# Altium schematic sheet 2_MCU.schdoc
size 309 x 223 mm; Symbol: Artery_A4; Device: Artery_A4; @Project Name: AT-START-M412; @Page Count: 4; @Create Date: 2024-06-20; Company: Artery Technology; Drawed: SD; Version: 1.0; Page Size: A4; @Update Date: 2024-08-06; @Page No: 2; @Schematic Name: AT-START-M412-V1.0; @Page Name: MCU; @Board Name: AT-START-M412-V1.0; @Create Time: 16:55:15; @Update Time: 16:25:14
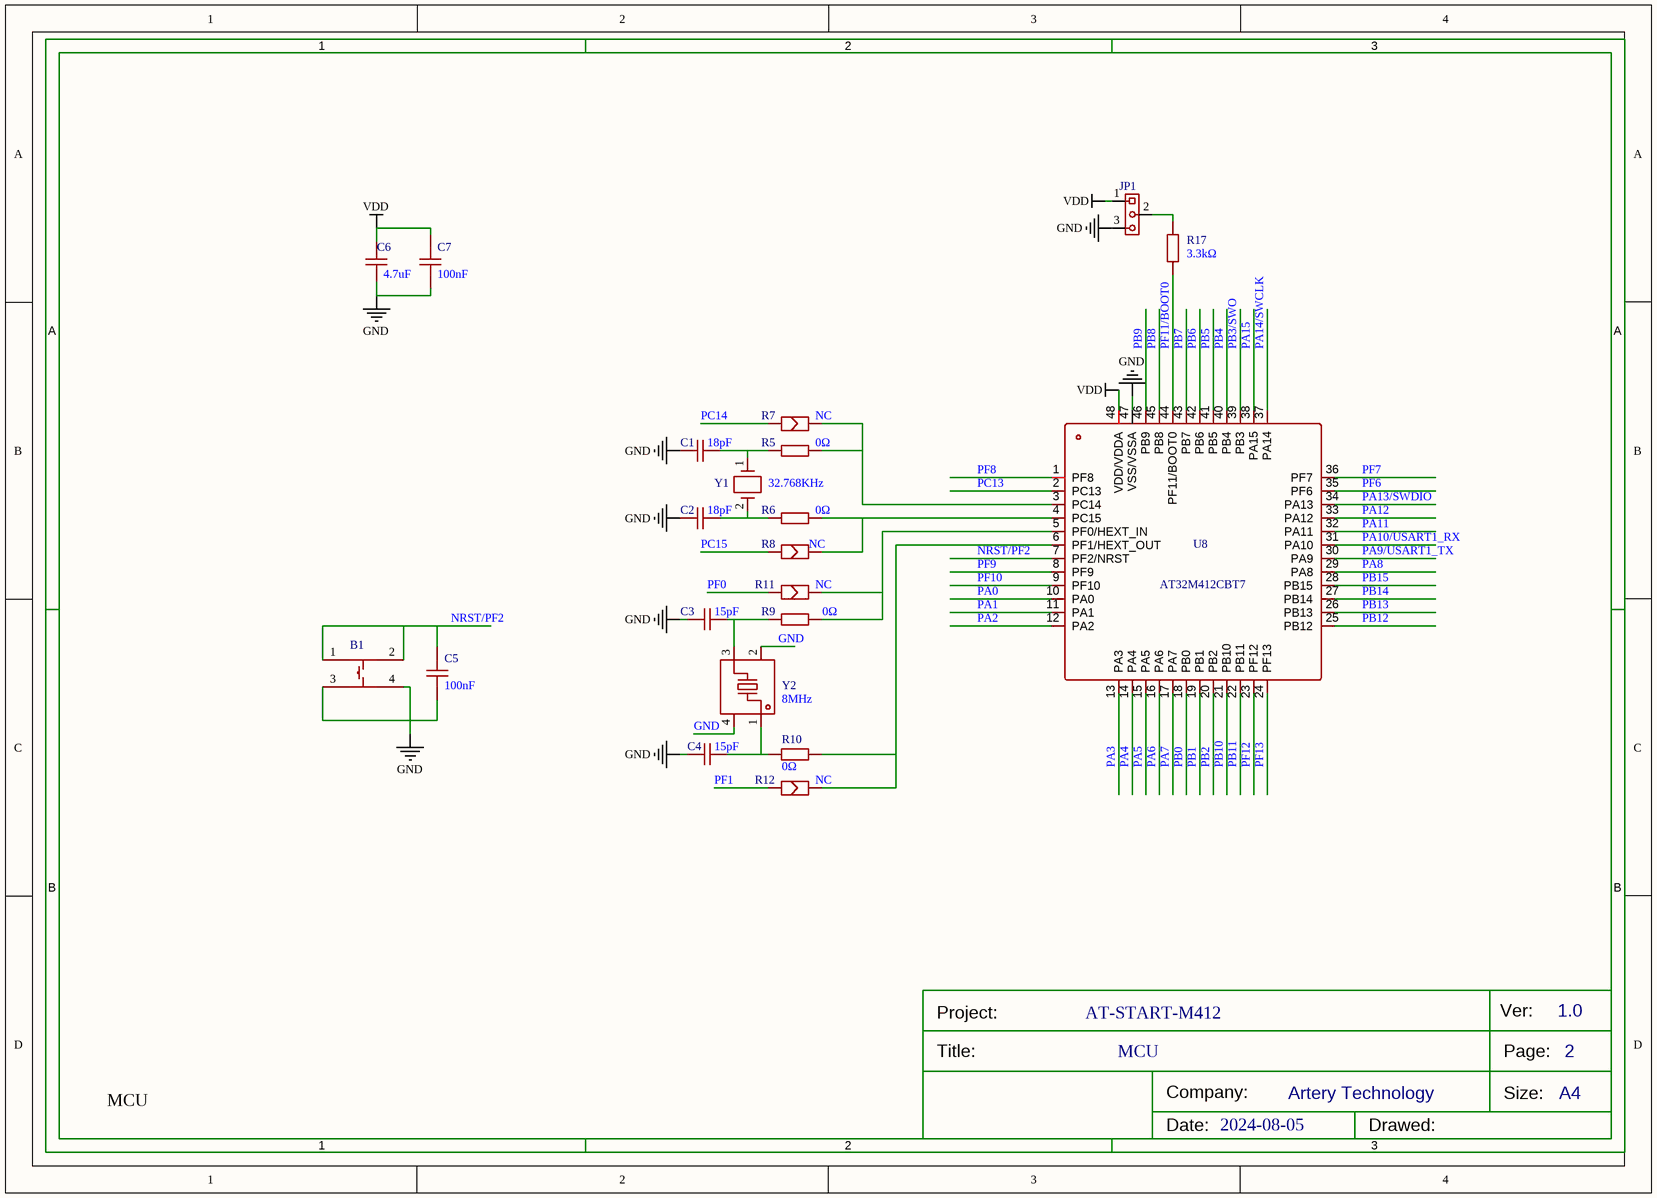
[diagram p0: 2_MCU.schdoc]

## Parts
B1  TS-1002S-05026C  [KEY-SMD_4P-L6.0-W6.0-P4.50-LS9.0]  (value not drawn)
C1  18pF  [C0603]  (value not drawn)
C2  18pF  [C0603]  (value not drawn)
C3  15pF  [C0603]  (value not drawn)
C4  15pF  [C0603]  (value not drawn)
C5  100nF  [C0603]  (value not drawn)
C6  4.7uF  [C0603]  (value not drawn)
C7  100nF  [C0603]  (value not drawn)
JP1  2.54-1*3P针  [HDR-TH_3P-P2.54-V-M-1]  (value not drawn)
R5  0Ω  [SB-PAD_2]  (value not drawn)
R6  0Ω  [SB-PAD_2]  (value not drawn)
R7  NC  [SB-PAD_2]  (value not drawn)
R8  NC  [SB-PAD_2]  (value not drawn)
R9  0Ω  [SB-PAD_2]  (value not drawn)
R10  0Ω  [SB-PAD_2]  (value not drawn)
R11  NC  [SB-PAD_2]  (value not drawn)
R12  NC  [SB-PAD_2]  (value not drawn)
R17  3.3kΩ  [R0603]  (value not drawn)
U8  AT32M412CxT7  [LQFP-48_L7.0-W7.0-P0.50-LS9.0-BL]  (value not drawn)
Y1  32.768KHz  [XTAL_SOP - FC-12M]  (value not drawn)
Y2  8MHz  [CRYSTAL-SMD_4P-L3.2-W2.5-BL]  (value not drawn)

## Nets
GND: B1.3 B1.4 C1.1 C2.1 C3.1 C4.1 C5.1 C6.1 C7.1 JP1.3 U8.47(VSS/VSSA) Y2.2(GND) Y2.4(GND)
VDD: C6.2 C7.2 JP1.1 U8.48(VDD/VDDA)
NRST/PF2: B1.1 B1.2 C5.2 U8.7(PF2/NRST)
PA0: U8.10(PA0)
PA1: U8.11(PA1)
PA2: U8.12(PA2)
PA3: U8.13(PA3)
PA4: U8.14(PA4)
PA5: U8.15(PA5)
PA6: U8.16(PA6)
PA7: U8.17(PA7)
PA8: U8.29(PA8)
PA9/USART1_TX: U8.30(PA9)
PA10/USART1_RX: U8.31(PA10)
PA11: U8.32(PA11)
PA12: U8.33(PA12)
PA13/SWDIO: U8.34(PA13)
PA14/SWCLK: U8.37(PA14)
PA15: U8.38(PA15)
PB0: U8.18(PB0)
PB1: U8.19(PB1)
PB2: U8.20(PB2)
PB3/SWO: U8.39(PB3)
PB4: U8.40(PB4)
PB5: U8.41(PB5)
PB6: U8.42(PB6)
PB7: U8.43(PB7)
PB8: U8.45(PB8)
PB9: U8.46(PB9)
PB10: U8.21(PB10)
PB11: U8.22(PB11)
PB12: U8.25(PB12)
PB13: U8.26(PB13)
PB14: U8.27(PB14)
PB15: U8.28(PB15)
PC13: U8.2(PC13)
PC14: R7.1
PC15: R8.1
PF0: R11.1
PF1: R12.1
PF6: U8.35(PF6)
PF7: U8.36(PF7)
PF8: U8.1(PF8)
PF9: U8.8(PF9)
PF10: U8.9(PF10)
PF11/BOOT0: R17.1 U8.44(PF11/BOOT0)
PF12: U8.23(PF12)
PF13: U8.24(PF13)
NetC1_2: C1.2 R5.1 Y1.1
NetC2_2: C2.2 R6.1 Y1.2
NetC3_2: C3.2 R9.1 Y2.3
NetC4_2: C4.2 R10.1 Y2.1
NetJP1_2: JP1.2 R17.2
NetR5_2: R5.2 R7.2 U8.3(PC14)
NetR6_2: R6.2 R8.2 U8.4(PC15)
NetR9_2: R9.2 R11.2 U8.5(PF0/HEXT_IN)
NetR10_2: R10.2 R12.2 U8.6(PF1/HEXT_OUT)

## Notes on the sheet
- (near U8) AT32M412CBT7
- AT-START-M412
- MCU
- 2024-08-05

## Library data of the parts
B1 = TS-1002S-05026C: 电路结构:单刀单掷;按钮形状:圆形按钮;安装方式:立贴;开关长度:6mm;开关宽度:6mm;开关高度:5mm;触点电流:50mA;额定电压(DC):12V;带灯:-;机械寿命:-;; Manufacturer: XUNPU(讯普); Add into BOM: yes; Circuit: 单刀单掷; Actuator Style: 圆形按钮; Switch Length: 6mm; Switch Height: 5mm; Contact Current: 50mA; Voltage Rating (DC): 12V; Origin Footprint: KEY_SOP_6*6
C1 C2 = CL10C180JB8NNNC: 容值:18pF;精度:±5%;额定电压:50V;材质(温度系数):C0G;; Manufacturer: SAMSUNG(三星); Add into BOM: yes; Tolerance: ±5%; Voltage Rated: 50V; Temperature Coefficient: C0G
C3 C4 = CL10C150JB8NNNC: 容值:15pF;精度:±5%;额定电压:50V;材质(温度系数):C0G;; Manufacturer: SAMSUNG(三星); Add into BOM: yes; Tolerance: ±5%; Voltage Rated: 50V; Temperature Coefficient: C0G
C5 C7 = CC0603KRX7R9BB104: 容值:100nF;精度:±10%;额定电压:50V;材质(温度系数):X7R;; Manufacturer: YAGEO(国巨); Add into BOM: yes; Tolerance: ±10%; Voltage Rated: 50V; Temperature Coefficient: X7R
C6 = CL10A475KO8NNNC: 容值:4.7uF;精度:±10%;额定电压:16V;材质(温度系数):X5R;; Manufacturer: SAMSUNG(三星); Add into BOM: yes; Tolerance: ±10%; Voltage Rated: 16V; Temperature Coefficient: X5R
JP1 = 2.54-1*3P针: 插针结构:1x3P;间距:2.54mm;行距:-;圆针/方针:方针;安装类型:直插;排数:单排;总PIN位数:3P;额定电流:3A;额定电压:-;配合针长度:-;塑高:-;端接针长度:-;触头材质:-;触头镀层:-;工作温度范围:-40℃~+105℃;颜色:黑色;; Manufacturer: BOOMELE(博穆精密); Symbol: Header-Male-2.54_1x3; Add into BOM: yes; Pin Structure: 1x3P; Pitch: 2.54mm; Circluar Pins/Square Pins: 方针; Current Rating (Max): 3A; Origin Footprint: HEADER 1X2
R5 R6 R9 R10 = 0603WAF0000T5E: 电阻类型:厚膜电阻;阻值:0Ω;精度:±1%;功率:100mW;最大工作电压:75V;; Manufacturer: UNI-ROYAL(厚声); Add into BOM: yes; Tolerance: ±1%; Power(Watts): 100mW; Overload Voltage (Max): 75V; Origin Footprint: SB-PAD
R7 R8 R11 R12 = SB_PAD: 贴片电阻0R,1/10W,5%,0603; Symbol: SB-PAD; Convert to PCB: yes
R17 = 0603WAF3301T5E: 电阻类型:厚膜电阻;阻值:3.3kΩ;精度:±1%;功率:100mW;最大工作电压:75V;温度系数:±100ppm/℃;; Manufacturer: UNI-ROYAL(厚声); Symbol: 0603WAF1002T5E; Add into BOM: yes; Tolerance: ±1%; Power(Watts): 100mW; Overload Voltage (Max): 75V
U8 = AT32M412CxT7: 由官方提供; Manufacturer: ArteryTechnology; Add into BOM: yes
Y1 = 32.768KHz: 32.768KHz贴片晶振 TZ2528C 2012 12.5pf 20ppm; Symbol: 32.768KHz,CRY,30PPM,Size_3X8; Add into BOM: yes
Y2 = CJ13-080001210B20: 频率:8MHz;常温频差:±10ppm;外接负载电容:12pF;; Manufacturer: CJ(江苏长电/长晶); Add into BOM: yes; Normal temperature Frequency Tolerance: ±10ppm; External load capacitor: 12pF; Crystal Type: 贴片晶振; Frequency Stability(Full temperature range): ±30ppm; Equivalent Series Resistance (ESR): 100Ω; Origin Footprint: SMD_5032_4P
